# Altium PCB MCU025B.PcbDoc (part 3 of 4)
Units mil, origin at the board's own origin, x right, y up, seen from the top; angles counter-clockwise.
Board outline 2300 x 6150 mil, 6 copper layers (Top Signal, GND, Middle Signal, PWR, GND2, Bottom Signal), stack 61.64 mil thick; 237 components, 197 nets, 910 pads, 404 vias.
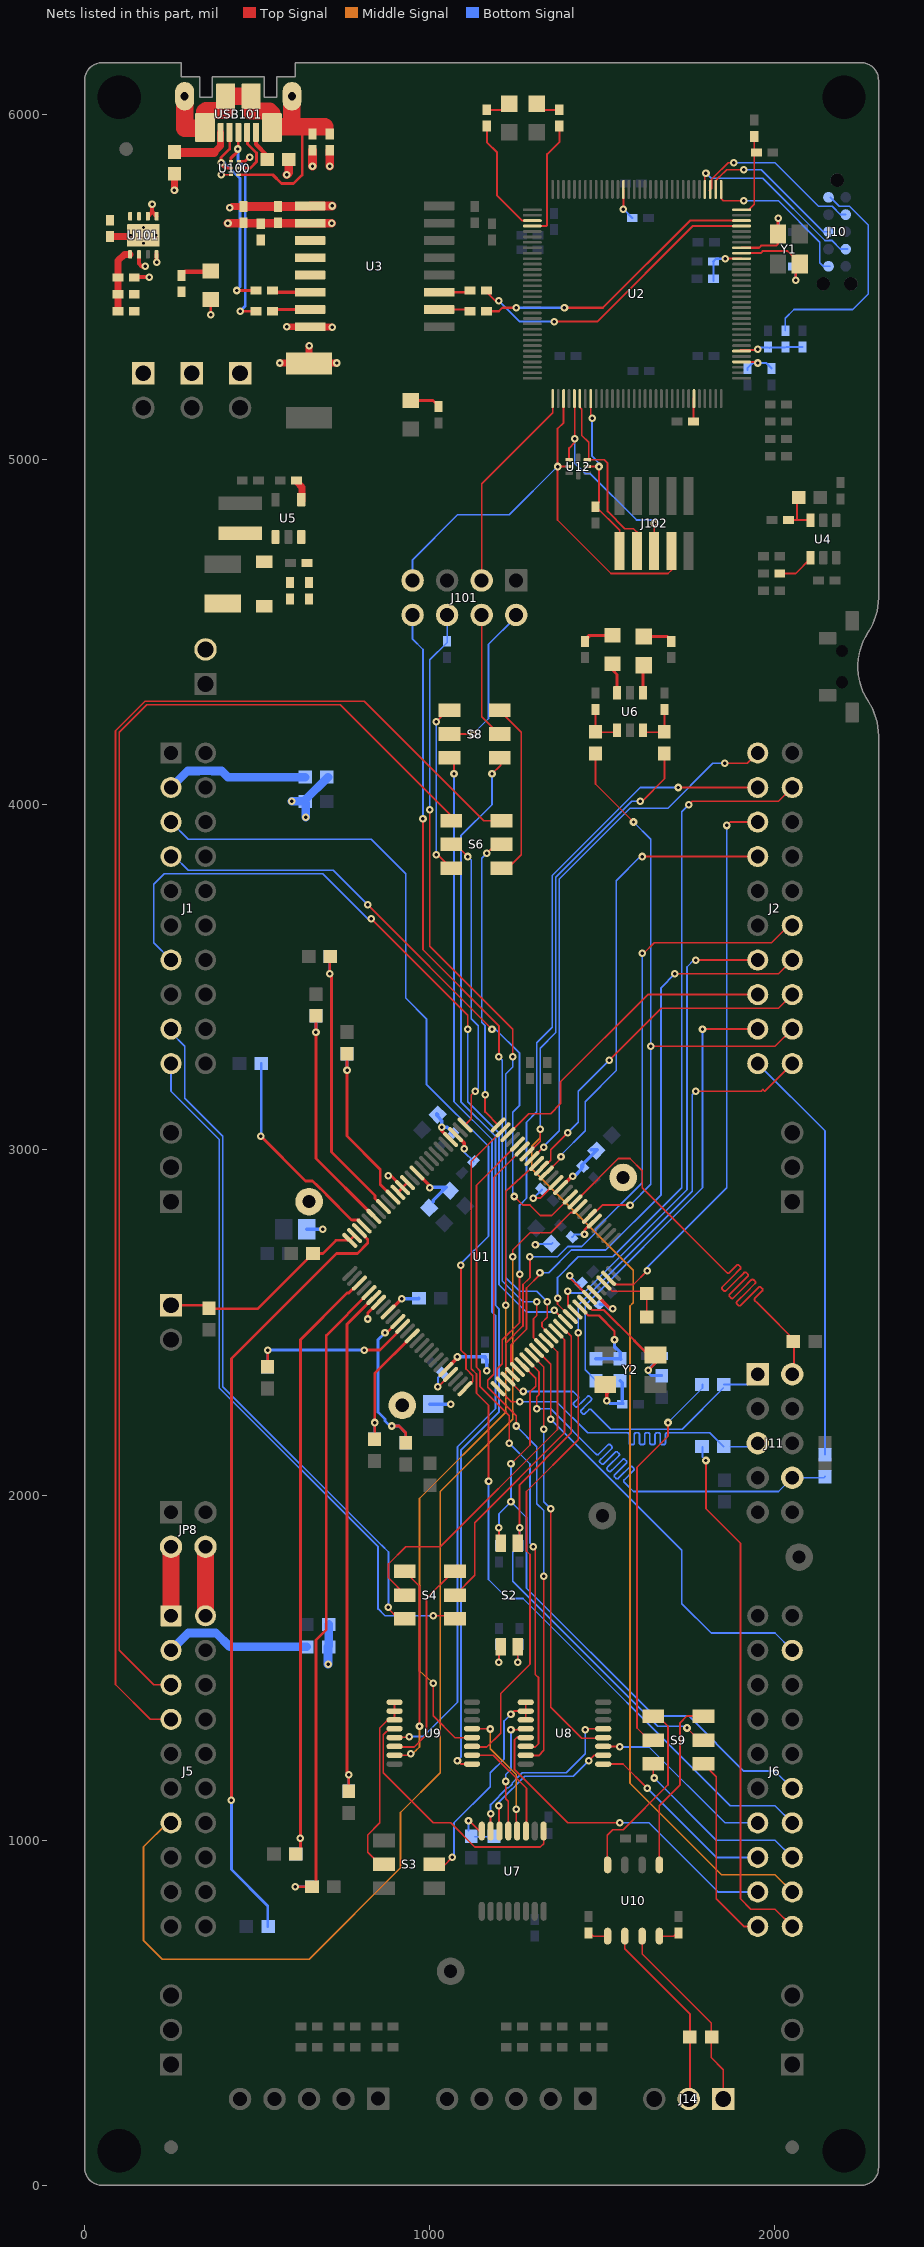
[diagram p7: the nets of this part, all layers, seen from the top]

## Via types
v1: diameter 22, hole 10, Top Signal to Bottom Signal, tented both sides, 400 vias
v2: diameter 19.68, hole 7.87, Top Signal to Bottom Signal, 4 vias

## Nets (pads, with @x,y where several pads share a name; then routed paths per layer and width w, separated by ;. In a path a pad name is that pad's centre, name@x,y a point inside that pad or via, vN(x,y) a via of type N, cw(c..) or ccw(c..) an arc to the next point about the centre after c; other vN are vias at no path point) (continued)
GPIO7_FSITXCLK: J11.2 R45.1 U1.84 | length 1583.5
  Top Signal w5: U1.84@1420.73,2849.38 1546.35,2975 1580,2975 1615,2940 1615,2890 1858.94,2646.06 1861.06,2643.94 ccw(c1864.24,2647.12) 1867.43,2643.94 1889.22,2665.73 cw(c1892.4,2662.55) 1895.58,2665.73 1899.83,2661.49 cw(c1896.64,2658.31) 1899.83,2655.12 1874.85,2630.15 1847.3,2602.6 ccw(c1850.48,2599.42) 1847.3,2596.24 1851.54,2591.99 ccw(c1854.73,2595.17) 1857.91,2591.99 1885.46,2619.54 1910.43,2644.52 cw(c1913.61,2641.33) 1916.8,2644.52 1921.04,2640.27 cw(c1917.86,2637.09) 1921.04,2633.91 1896.06,2608.94 1868.51,2581.39 ccw(c1871.7,2578.2) 1868.51,2575.02 1872.76,2570.78 ccw(c1875.94,2573.96) 1879.12,2570.78 1906.67,2598.33 1931.64,2623.3 cw(c1934.83,2620.12) 1938.01,2623.3 1942.25,2619.06 cw(c1939.07,2615.88) 1942.25,2612.7 1917.28,2587.72 1889.73,2560.17 ccw(c1892.91,2556.99) 1889.73,2553.81 1893.97,2549.57 ccw(c1897.15,2552.75) 1900.33,2549.57 1927.88,2577.12 1952.86,2602.09 cw(c1956.04,2598.91) 1959.22,2602.09 1963.46,2597.85 cw(c1960.28,2594.67) 1963.46,2591.48 1941.67,2569.69 ccw(c1944.85,2566.51) 1941.67,2563.33 1948.27,2556.73 1970,2535 2055,2450 2055,2355 J11.2@2050,2350
GPIO8: J2.38 U1.74 | length 1615.3
  Top Signal w5: U1.74@1518.17,2628.06 1536.23,2610 1590,2610 v1(1630,2650) ; v1(1860,3940) 1870,3950 J2.38@1950,3950
  Bottom Signal w5: v1(1630,2650) 1630,2660 1860,2890 v1(1860,3940)
GPIO9: J2.37 U1.90 | length 1370.1
  Top Signal w5: U1.90@1337.22,2932.89 1380,2975.68 v1(1380,2980) ; v1(1615,3850) J2.37@1950,3850
  Bottom Signal w5: v1(1380,2980) 1380,2985 1450,3055 1450,3140 1540,3230 1540,3780 1610,3850 v1(1615,3850)
GPIO10: J2.40 U1.93 | length 1570.2
  Top Signal w5: U1.93@1295.46,2974.65 1328.8,3008 v1(1330,3008) ; v1(1855,4120) 1920,4120 J2.40@1950,4150
  Bottom Signal w5: v1(1330,3008) 1330,3010 1375,3055 1375,3785 1580,3990 1690,3990 1820,4120 v1(1855,4120)
GPIO11: J2.39 U1.52 | length 2246.7
  Top Signal w5: U1.52@1211.94,2321.83 1195.45,2338.32 1195.45,2365.45 1210,2380 1210,2450 1260,2500 v1(1260,2640) ; v1(1720,4050) J2.39@1950,4050
  Bottom Signal w5: v1(1260,2640) 1260,2840 1280,2860 1280,3080 1310,3110 1310,3310 1355,3355 1355,3795 1610,4050 v1(1720,4050)
GPIO12_BP: J6.11 R47.2 | length 1538.7
  Top Signal w5: v1(1800,2100) 1800,1960 1900,1860 1900,830 1930,800 2000,800 J6.11@2050,750
  Bottom Signal w5: R47.2@1790,2140 1790,2110 v1(1800,2100)
GPIO12_FSIRXD0: J11.5 R47.1 U1.51 | length 1046.4
  Top Signal w5: U1.51@1198.02,2307.91 1235.93,2270 v1(1260,2270)
  Bottom Signal w5: v1(1260,2270) 1367,2270 1457,2180 1555,2180 1562.5,2180 1573,2180 cw(c1573,2175.5) 1577.5,2175.5 1577.5,2150.74 ccw(c1582,2150.74) 1582,2146.24 1588,2146.24 ccw(c1588,2150.74) 1592.5,2150.74 1592.5,2175.5 cw(c1597,2175.5) 1597,2180 1603,2180 cw(c1603,2175.5) 1607.5,2175.5 1607.5,2150.74 ccw(c1612,2150.74) 1612,2146.24 1618,2146.24 ccw(c1618,2150.74) 1622.5,2150.74 1622.5,2175.5 cw(c1627,2175.5) 1627,2180 1633,2180 cw(c1633,2175.5) 1637.5,2175.5 1637.5,2150.74 ccw(c1642,2150.74) 1642,2146.24 1648,2146.24 ccw(c1648,2150.74) 1652.5,2150.74 1652.5,2175.5 cw(c1657,2175.5) 1657,2180 1663,2180 cw(c1663,2175.5) 1667.5,2175.5 1667.5,2150.74 ccw(c1672,2150.74) 1672,2146.24 1678,2146.24 ccw(c1678,2150.74) 1682.5,2150.74 1682.5,2175.5 cw(c1687,2175.5) 1687,2180 1690,2180 1811.5,2180 R47.1@1851.5,2140 ; R47.1@1870,2140 1940,2140 J11.5@1950,2150
GPIO13: J1.3 U1.50 | length 2390
  Top Signal w5: v1(1090,2666) 1090,2420 1105,2405 1105,2365 1124.07,2345.93 1124.07,2330 U1.50@1101.98,2307.91
  Bottom Signal w5: J1.3@250,3950 300,3900 830,3900 930,3800 930,3440 990,3380 990,3190 1170,3010 1170,2750 1090,2670 v1(1090,2666)
GPIO14: U1.96 U8.14 | length 1899.3
  Top Signal w5: v1(1230,2150) 1230,2230 1145,2315 1145,2360 1135,2370 1135,2897.71 U1.96@1253.7,3016.41 ; U8.14@1280,1270 1305,1270 1315,1280 1315,1470 1305,1480 1305,1845 v1(1300,1850)
  Bottom Signal w5: v1(1230,2150) 1290,2090 1290,1860 v1(1300,1850)
GPIO14_BP: J6.32 U8.13 | length 972.8
  Top Signal w5: U8.13@1277.8,1297.2 1252.2,1297.2 1245,1290 1245,1205 1400,1050 v1(1550,1050)
  Bottom Signal w5: v1(1550,1050) 1635,1050 1835,850 J6.32@1950,850
GPIO14_Q2A: U7.5 U8.12 | length 348.1
  Top Signal w5: v1(1220,1170) 1220,1120 1227.2,1112.8 U7.5@1227.2,1026.14 ; v1(1235,1320) U8.12@1280,1320
  Bottom Signal w5: v1(1220,1170) 1220,1190 1235,1205 v1(1235,1320)
GPIO15: U1.95 U8.15 | length 1907.3
  Top Signal w5: 1167.61,2329.89 1167.61,2312.39 1250,2230 v1(1250,2200) ; 1167.61,2330 1167.61,2332.61 1185,2350 1185,2919.87 U1.95@1267.62,3002.49 ; U8.15@1280,1245 1315,1245 1330,1260 v1(1330,1765)
  Bottom Signal w5: v1(1250,2200) 1310,2140 1310,1975 1330,1955 v1(1330,1765)
GPIO15_BP: J6.33 U8.1 | length 559.8
  Top Signal w5: U8.1@1502.2,1220.43 1559.57,1220.43 v1(1630,1150)
  Bottom Signal w5: v1(1630,1150) 1830,950 J6.33@1950,950
GPIO15_Q2B: U7.6 U8.2 | length 438.7
  Top Signal w5: U7.6@1200,1030 v1(1200,1100) ; v1(1460,1230) 1476.02,1246.02 U8.2@1502.2,1246.02
  Bottom Signal w5: v1(1200,1100) 1200,1110 1231.5,1141.5 1231.81,1141.5 1248.5,1158.2 1248.5,1158.5 1275,1185 1415,1185 v1(1460,1230)
GPIO16: J2.15 U1.54 | length 1921.9
  Top Signal w5: U1.54@1240.33,2349.67 U1.54@1239.78,2349.67 1239.78,2350.22 1220,2370 1220,2440 1270,2490 1270,2610 1290,2630 v1(1290,2690) ; v1(1615,3570) 1618,3570 1619,3569 1650,3600 1990,3600 J2.15@2040,3650
  Bottom Signal w5: v1(1290,2690) 1370,2690 1400,2720 1440,2720 1480,2760 1480,2770 1615,2905 v1(1615,3570)
GPIO17: J2.14 U1.55 | length 1781.5
  Top Signal w5: U1.55@1253.7,2363.59 1235,2382.29 1235,2435 1280,2480 1280,2600 1320,2640 1319,2641 v1(1319,2644) ; v1(1710,3510) 2010,3510 J2.14@2050,3550
  Bottom Signal w5: v1(1319,2644) 1344,2644 1410,2710 1510,2710 1670,2870 1670,3470 v1(1710,3510)
GPIO18_BP: J2.32 R28.1 | length 1332.3
  Top Signal w5: v1(1790,3350) J2.32@1950,3350
  Bottom Signal w5: R28.1@1481.21,2331.43 1450,2362.65 1450,2550 1790,2890 v1(1790,3350)
GPIO18_X2: R28.2 R31.2 U1.68 | length 355.5
  Top Signal w6: U1.68@1434.65,2544.54 1459.2,2520 1490,2520 1535,2475 v1(1535,2450)
  Bottom Signal w10: v1(1535,2450) 1535,2430 1551.21,2413.79 R31.2@1551.21,2394.43 ; R31.2@1550,2395 1549.43,2394.43 R28.2@1481.21,2394.43 1550,2394.42 R31.2@1551.21,2394.43
GPIO22: J5.7 U1.83 | length 3427.8
  Top Signal w5: v1(1240,2690) 1240,2710 1290,2760 1350,2760 1408.5,2818.5 1417.7,2818.5 U1.83@1434.65,2835.46
  Middle Signal w5: J5.7@250,1050 240,1050 170,980 170,710 225,655 650,655 915,920 915,1080 1030,1195 1030,2010 1240,2220 v1(1240,2690)
GPIO23: J2.12 R38.1 U1.81 | length 1962.8
  Top Signal w5: U1.81@1462.49,2807.62 1467.62,2807.62 1500,2840 v1(1580,2840) ; R38.1@1480,4150 R38.1@1480,4148.5 1480,4060 v1(1590,3950) ; v1(1640,3300) 2000,3300 J2.12@2050,3350
  Bottom Signal w5: v1(1580,2840) 1640,2900 v1(1640,3300) 1640,3900 v1(1590,3950)
GPIO24: J6.15 R33.1 S2.2 U1.56 | length 1908
  Top Signal w5: S2.2@1200,1860 v1(1200,1905) ; v1(1235,2090) 1290,2145 1290,2298.84 1306.5,2315.34 1306.5,2338.63 U1.56@1267.62,2377.51
  Bottom Signal w5: R33.1@1200,1853.62 v1(1200,1905) 1200,1945 v1(1235,1980) ; v1(1235,2090) v1(1235,1980) ; J6.15@2050,1150 2000,1200 1910,1200 1750,1360 1650,1360 1280,1730 1280,1935 v1(1235,1980)
GPIO25_BP: J2.31 R72.2 | length 1214.3
  Bottom Signal w5: J2.31@1950,3250 2145,3055 R72.2@2145,2116.5
GPIO25_FSITXD1: J11.8 R72.1 U1.57 | length 1516.7
  Top Signal w5: U1.57@1281.54,2391.43 1316.5,2356.47 1316.5,2291.5 1310,2285 v1(1310,2250)
  Bottom Signal w5: v1(1310,2250) 1350,2250 1480,2120 1482.12,2117.88 ccw(c1485.3,2121.06) 1488.49,2117.88 1516.08,2145.48 cw(c1519.27,2142.3) 1522.45,2145.48 1526.69,2141.24 cw(c1523.51,2138.05) 1526.69,2134.87 1495.91,2104.09 1492.93,2101.11 ccw(c1496.11,2097.93) 1492.93,2094.75 1497.17,2090.5 ccw(c1500.35,2093.69) 1503.54,2090.5 1506.52,2093.48 1537.3,2124.26 cw(c1540.48,2121.08) 1543.66,2124.26 1547.9,2120.02 cw(c1544.72,2116.84) 1547.9,2113.66 1517.12,2082.88 1514.14,2079.9 ccw(c1517.32,2076.71) 1514.14,2073.53 1518.39,2069.29 ccw(c1521.57,2072.47) 1524.75,2069.29 1527.73,2072.27 1558.51,2103.05 cw(c1561.69,2099.87) 1564.87,2103.05 1569.12,2098.81 cw(c1565.94,2095.63) 1569.12,2092.44 1538.34,2061.66 1535.36,2058.68 ccw(c1538.54,2055.5) 1535.36,2052.32 1539.6,2048.08 ccw(c1542.78,2051.26) 1545.96,2048.08 1548.94,2051.06 1579.72,2081.84 cw(c1582.91,2078.66) 1586.09,2081.84 1590.33,2077.6 cw(c1587.15,2074.41) 1590.33,2071.23 1562.73,2043.63 ccw(c1565.91,2040.45) 1562.73,2037.27 1567.36,2032.64 1590,2010 2010,2010 J11.8@2050,2050 2141.5,2050 R72.1@2145,2053.5
GPIO26: U1.58 U8.4 | length 1235.2
  Top Signal w5: U1.58@1295.46,2405.35 1330,2370.81 v1(1330,2190) ; v1(1350,1960) 1350,1750 1350,1730 1350,1385 1440,1295 U8.4@1505,1295
  Bottom Signal w5: v1(1330,2190) 1330,1980 v1(1350,1960)
GPIO26_BP: J6.34 U8.3 | length 539.6
  Top Signal w5: U8.3@1502.2,1271.61 1548.39,1271.61 v1(1550,1270)
  Bottom Signal w5: v1(1550,1270) 1635,1270 1855,1050 J6.34@1950,1050
GPIO26_Q2I: U7.7 U8.5 | length 534.8
  Top Signal w5: v1(1176,1077) 1176,1034 U7.7@1180,1030 ; v1(1450,1320) 1452.8,1322.8 U8.5@1502.2,1322.8
  Bottom Signal w5: v1(1176,1077) 1176,1103 1224.5,1151.5 1227.66,1151.5 1238.5,1162.34 1238.5,1165.5 1268,1195 1395,1195 1450,1250 v1(1450,1320)
GPIO27: J6.19 U1.59 | length 1291.5
  Top Signal w5: U1.59@1309.38,2419.27 1350,2378.65 v1(1350,2220)
  Bottom Signal w5: v1(1350,2220) 1730,1840 1730,1685 1815,1600 2000,1600 J6.19@2050,1550 J6.19@2055,1545
GPIO28: S6.2 U1.1 | length 868.5
  Top Signal w5: S6.2@1065,3885 1075,3885 v1(1110,3850) ; U1.1@1100,3070 1120,3090 1120,3159 v1(1131,3170)
  Bottom Signal w5: v1(1110,3850) 1120,3840 1120,3380 1140,3360 1140,3179 v1(1131,3170)
GPIO28_BP: J5.3 S6.1 | length 3994.1
  Top Signal w5: J5.3@250,1450 200,1450 100,1550 100,4210 180,4290 740,4290 1062.17,3967.83 S6.1@1062.17,3953.9
GPIO28_SCIRX: S6.3 S8.6 | length 507.8
  Top Signal w5: v1(1018.5,3854.86) 1018.27,3855.09 1018.27,3860 S6.3@1062.17,3816.1 ; v1(1018.5,4240.14) 1018.64,4240 1048.64,4270 S8.6@1060,4270
  Bottom Signal w5: v1(1018.5,3854.86) 1018.5,4233.5 1020,4235 1020,4238.64 v1(1018.5,4240.14)
GPIO29: S6.5 U1.100 | length 867.3
  Top Signal w5: v1(1160,3160) 1160,3110 U1.100@1200,3070 ; v1(1165,3860) 1190,3885 S6.5@1205,3885
  Bottom Signal w5: v1(1160,3160) 1160,3360 1150,3370 1150,3845 v1(1165,3860)
GPIO29_BP: J5.4 S6.4 | length 4264
  Top Signal w5: J5.4@250,1350 190,1350 89,1451 89,4214.56 174.44,4300 810,4300 1156.1,3953.9 S6.4@1207.83,3953.9
GPIO29_SCITX: S6.6 S8.3 | length 520.2
  Top Signal w5: S8.3@1200,4275 1265,4210 1265,3855 1226.1,3816.1 S6.6@1207.83,3816.1
GPIO30: J2.33 U1.98 | length 932.6
  Top Signal w5: U1.98@1225.86,3045.86 U1.98@1225.86,3044.25 1286.61,3105 ; 1285,3105 1286.61,3105 ; J2.33@1950,3450 1631.61,3450 1378.31,3196.69 1378.31,3133.31 1350,3105 1286.61,3105
GPIO31: J6.14 U1.99 | length 2534
  Top Signal w5: v1(1170,2040) 1170,2260 1135,2295 1135,2350.56 1120,2365.56 1120,2966.23 U1.99@1211.94,3058.17
  Bottom Signal w5: v1(1170,2040) 1170,1755 1225,1700 1270,1700 1870,1100 2000,1100 J6.14@2050,1050
GPIO32: R34.1 S2.1 S9.5 U1.64 | length 1598.9
  Top Signal w5: S2.1@1260,1860 v1(1260,1905) 1260,2030 1410,2180 1410,2460 1381.14,2488.86 U1.64@1378.97,2488.86 ; v1(1745,1325) S9.5@1780,1290
  Bottom Signal w5: v1(1260,1905) R34.1@1260,1853.62 1240,1833.62 1240,1750 1660,1330 1740,1330 v1(1745,1325)
GPIO32_BP: J6.31 S9.6 | length 559.6
  Top Signal w5: S9.6@1792.83,1221.1 1830,1183.94 1830,830 1910,750 J6.31@1950,750
GPIO32_CANTX: S9.4 U10.1 | length 513.1
  Top Signal w5: U10.1@1665,925 U10.1@1665,928.35 1665,1100 1725,1160 1725,1340 1745,1360 S9.4@1790,1360
GPIO33_ALT: R46.2 S9.2 | length 1135.4
  Top Signal w5: S9.2@1647.17,1290 1635,1290 1600,1325 1600,2080 1690,2170 v1(1690,2210)
  Bottom Signal w5: v1(1690,2210) 1790,2310 R46.2@1790,2320
GPIO33_BP: J6.13 S9.3 | length 537.5
  Top Signal w5: S9.3@1647.17,1221.1 1647.17,1182.83 v1(1650,1180)
  Bottom Signal w5: v1(1650,1180) 1830,1000 2000,1000 J6.13@2050,950
GPIO33_CANRX: S9.1 U10.4 | length 545.9
  Top Signal w5: U10.4@1514,927 1514,1014 1530,1030 1560,1030 1690,1160 1690,1330 1660,1360 S9.1@1650,1360
GPIO33_FSIRXCLK: J11.1 R46.1 U1.53 | length 1066
  Top Signal w5: U1.53@1225.86,2335.75 1261.61,2300 v1(1270,2300)
  Bottom Signal w5: 1349.61,2300 v1(1270,2300) 1415,2300 ; 1410,2300 1415,2300 ; R46.1@1850,2310 1730.82,2190.82 1524.18,2190.82 1469.59,2245.41 1467.47,2247.53 ccw(c1464.28,2244.35) 1461.1,2247.53 1448.89,2235.32 cw(c1445.71,2238.5) 1442.53,2235.32 1438.28,2239.56 cw(c1441.47,2242.75) 1438.28,2245.93 1453.68,2261.32 1467.23,2274.87 ccw(c1464.05,2278.06) 1467.23,2281.24 1462.99,2285.48 ccw(c1459.81,2282.3) 1456.62,2285.48 1443.07,2271.93 1427.68,2256.53 cw(c1424.5,2259.72) 1421.31,2256.53 1417.07,2260.78 cw(c1420.25,2263.96) 1417.07,2267.14 1429.28,2279.35 ccw(c1426.1,2282.54) 1429.28,2285.72 1422.5,2292.5 1415,2300 ; R46.1@1851.5,2320 1920,2320 J11.1@1950,2350
GPIO34: J6.12 R39.1 U1.94 | length 3980.7
  Top Signal w5: U1.94@1281.54,2988.57 1283.57,2988.57 1320,3025 v1(1320,3060) ; v1(1610,4010) 1615,4010 1680,4075 1680,4140 R39.1@1690,4150
  Middle Signal w5: v1(1320,3060) 1320,3035 1295,3010 1295,2945 1589,2651 1589,2556.75 1580,2547.75 1580,1165 1845,900 2000,900 J6.12@2050,850
  Bottom Signal w5: v1(1320,3060) 1320,3295 1365,3340 1365,3790 1585,4010 v1(1610,4010)
GPIO35: S4.5 U1.63 | length 906.7
  Top Signal w5: S4.5@1072.83,1710 1130,1767.17 1130,1920 1390,2180 1390,2450 U1.63@1365.06,2474.94
GPIO35_ALT: S4.4 U9.14 | length 615
  Top Signal w5: U9.14@900,1270 955,1270 990,1305 990,1700 1068.9,1778.9 S4.4@1072.83,1778.9
GPIO35_BP: J1.10 S4.6 | length 2071
  Top Signal w5: v1(1010,1650) 1070,1650 S4.6@1080,1640
  Bottom Signal w5: J1.10@250,3250 250,3170 390,3030 390,2310 850,1850 850,1670 870,1650 v1(1010,1650)
GPIO35_Q1A: U7.1 U9.12 | length 736.5
  Top Signal w5: U9.12@895,1325 885,1325 865,1305 865,1195 1010,1050 1060,1050 1130,980 1320,980 1330,990 U7.1@1330,1020
GPIO35_SCIRX: S8.4 U9.13 | length 3063.8
  Top Signal w5: U9.13@895.59,1295 U9.13@897.8,1297.2 ; U9.13@898,1298 938,1298 v1(940,1300) ; S8.4@1055,4135 1070,4120 v1(1070,4090)
  Bottom Signal w5: v1(940,1300) 980,1300 1080,1400 1080,2140 1190,2250 1190,2520 1180,2530 1180,3030 1070,3140 v1(1070,4090)
GPIO37: S4.2 U1.61 | length 1032.9
  Top Signal w5: S4.2@930,1710 880,1760 880,1800 930,1850 1030,1850 1370,2190 1370,2414.32 U1.61@1337.22,2447.11
GPIO37_ALT: S4.1 U9.15 | length 608.8
  Top Signal w5: U9.15@897.8,1246.02 941.02,1246.02 v1(945,1250) ; S4.1@927.17,1778.9 970,1736.06 970,1340 v1(970,1330)
  Middle Signal w5: v1(945,1250) 950,1250 960,1260 970,1270 v1(970,1330)
GPIO37_BP: J1.9 S4.3 | length 2003.9
  Top Signal w5: v1(880,1675) 880,1670 910,1640 S4.3@930,1640
  Bottom Signal w5: J1.9@250,3350 250,3340 290,3300 290,3150 400,3040 400,2314.14 860,1854.14 860.86,1854.14 880,1835 v1(880,1675)
GPIO37_Q1B: U7.3 U9.2 | length 317.6
  Top Signal w5: U9.2@1122.2,1246.02 1183.98,1246.02 1280,1150 U7.3@1280,1030
GPIO37_SCITX: S8.1 U9.1 | length 3099.1
  Top Signal w5: v1(1080,1230) 1089.57,1220.43 U9.1@1122.2,1220.43 ; v1(1180,4090) 1205,4115 S8.1@1205,4140
  Bottom Signal w5: v1(1080,1230) 1090,1240 1090,2130 1200,2240 1200,2540 1190,2550 1190,3040 1090,3140 1090,3910 1180,4000 v1(1180,4090)
GPIO39: J2.13 U1.91 | length 1005.4
  Top Signal w5: U1.91@1323.3,2946.81 1326.81,2946.81 1350,2970 1350,3000 v1(1400,3050) ; v1(1520,3260) 1670,3410 2010,3410 J2.13@2050,3450
  Bottom Signal w5: v1(1400,3050) 1430,3080 1430,3170 v1(1520,3260)
GPIO40: J1.4 U1.85 | length 1882.5
  Top Signal w5: v1(820,3710) v1(1180,3350) ; v1@1245,2869.34 v1(1245,2865) 1270,2840 1290,2840 1320,2810 1353.52,2810 U1.85@1406.81,2863.3
  Bottom Signal w5: J1.4@250,3850 260,3850 300,3810 720,3810 v1(820,3710) ; v1(1180,3350) 1190,3350 1260,3280 1260,3129.11 1240,3109.11 1240,2870 v1(1245,2865)
GPIO56: J1.7 U1.65 | length 2394.5
  Top Signal w5: v1(830,3670) 1110,3390 v1(1110,3350) ; v1(1360,2535) 1363,2535 1364,2534 1364.32,2534.32 1365.68,2534.32 1365.68,2530 U1.65@1392.89,2502.78
  Bottom Signal w5: J1.7@250,3550 200,3600 200,3770 230,3800 690,3800 820,3670 v1(830,3670) ; v1(1110,3350) 1110,3140 1200,3050 1200,2610 1280,2530 1355,2530 v1(1360,2535)
GPIO57: J2.19 U1.66 | length 2035.2
  Top Signal w5: v1(1370,2570) 1370,2553.52 U1.66@1406.81,2516.7 ; v1(1750,4000) 1760,4010 2010,4010 J2.19@2050,4050
  Bottom Signal w5: v1(1370,2570) 1370,2630 1430,2690 1530,2690 1730,2890 1730,3980 v1(1750,4000)
GPIO58: J2.34 U1.67 | length 1397.6
  Top Signal w5: v1(1400,2590) 1400,2551.35 U1.67@1420.73,2530.62 ; v1(1770,3550) J2.34@1950,3550
  Bottom Signal w5: v1(1400,2590) 1405,2585 1445,2585 1745,2885 1745,3530 1765,3550 v1(1770,3550)
GPIO59: U1.92 U9.4 | length 1902
  Top Signal w5: v1(1010,1454.34) 1010,1360 1073,1297 U9.4@1124,1297 ; v1(1220,2550) 1220,2880 U1.92@1309.38,2960.73
  Middle Signal w5: v1(1010,1454.34) 1004.69,1459.65 970,1490 970,1990 1220,2240 v1(1220,2550)
GPIO59_BP: J2.11 U9.3 | length 2516.2
  Top Signal w5: U9.3@1125,1270 1165,1270 1205,1310 1205,1425 1290,1510 1290,1827.75 1280,1837.75 1280,2010 1430,2160 v1(1430,2470) ; v1(1770,3170) 1960,3170 1965,3175 1970,3170 J2.11@2050,3250
  Bottom Signal w5: v1(1430,2470) 1430,2550 1760,2880 1760,3160 v1(1770,3170)
GPIO59_Q1I: U7.4 U9.5 | length 405.4
  Top Signal w5: U9.5@1122.2,1322.8 1177.2,1322.8 v1@1180,1320 ; U7.4@1250,1030 v1(1250,1090) ; U7.4@1252.8,1002.8 U7.4@1252.8,1026.14
  Middle Signal w5: v1@1180,1320 1175,1315 1175,1265 1250,1190 v1(1250,1090)
  other v1: 1175,1322
ITCK: J10.4 U2.100 | length 549.3
  Top Signal w5: U2.100@1796.85,5783.15 1796.85,5826.85 v1(1800,5830)
  Bottom Signal w5: v1(1800,5830) 1815,5815 1965,5815 2145,5635 2165,5635 2165.47,5634.53 2190,5610 J10.4@2205,5610 J10.4@2210,5610
ITDI: J10.8 U2.98 | length 444.7
  Top Signal w5: U2.98@1828.35,5783.15 1828.35,5808.35 1831.66,5811.66 1831.66,5811.92 1838.94,5819.21 1839.21,5819.21 1860,5840 v1(1910,5840)
  Bottom Signal w5: v1(1910,5840) 1960,5840 2140,5660 J10.8@2155,5660 J10.8@2160,5660
ITDO: J10.6 U2.97 | length 459.4
  Top Signal w5: U2.97@1844.09,5783.15 1844.09,5755.91 1850,5750 v1(1910,5750)
  Bottom Signal w5: v1(1910,5750) 2010,5750 2130,5630 2130,5570 2140,5560 J10.6@2155,5560 J10.6@2160,5560
ITMS: J10.2 U2.99 | length 505.5
  Top Signal w5: U2.99@1810,5780 1815.91,5785.91 1815.91,5811.92 1823.19,5819.21 1823.39,5819.21 1864.18,5860 v1(1880,5860)
  Bottom Signal w5: v1(1880,5860) 2000,5860 2126,5734 2166,5734 2190,5710 J10.2@2205,5710
NetC3_1: C3.1 C4.1 D1.1 JP9.2 R7.2
NetC3_2: C3.2 R7.1 R9.2 U5.3
NetC8_1: C8.1 R6.1 U4.6 | length 134.6
  Top Signal w5: C8.1@2038.62,4825 2065,4825 ; R6.1@2070,4890 2063.62,4883.62 2063.62,4826.38 2065,4825 ; U4.6@2105,4825 2065,4825
NetC26_2: C26.2 R14.1 U1.18 | length 838.9
  Top Signal w8: R14.1@710,3560 v1(710,3510) 715,3505 715,2994 841.4,2867.6 841.4,2859.4 U1.18@865.35,2835.46
  Bottom Signal w8: v1(710,3510) C26.2@710,3560
NetC27_2: C27.2 R16.1 U1.30 | length 1887.6
  Top Signal w8: v1(610,865) R16.1@657.01,865 ; R16.1@658.5,865 R16.1@658.5,866.5 ; R16.1@660,865 670,875 670,1580 700,1610 700,2462.71 U1.30@823.59,2586.3
  Bottom Signal w8: v1(610,865) C27.2@658.5,865 C27.2@660,865
NetC28_2: C28.2 R17.1 U1.20 | length 700.8
  Top Signal w8: R17.1@670,3390 R17.1@670,3388.5 v1(670,3341) 670,2975.13 U1.20@837.51,2807.62
  Bottom Signal w8: v1(670,3341) C28.2@670,3388.5 C28.2@670,3390
NetC29_2: C29.2 R18.1 U1.31 | length 1515.1
  Top Signal w8: R18.1@765,1140 R18.1@765,1141.5 v1(765,1190) 760,1195 760,2494.87 U1.31@837.51,2572.38
  Bottom Signal w8: C29.2@765,1141.5 v1(765,1190)
NetC30_2: C30.2 R20.1 U1.16 | length 519.4
  Top Signal w8: R20.1@760,3280 R20.1@760,3278.5 v1(760,3231) 760,3040 856,2944 856,2900.48 U1.16@893.19,2863.3
  Bottom Signal w8: v1(760,3231) C30.2@760,3278.5
NetC31_2: C31.2 R21.1 U1.28 | length 1786.8
  Top Signal w8: R21.1@610,960 625,975 v1(625,1005) 625,2450 760,2585 765,2585 794.14,2614.14 U1.28@795.75,2614.14
  Bottom Signal w8: C31.2@611.5,960 610,961.5 625,976.5 v1(625,1005)
NetC32_1: C32.1 R19.2 U1.36 | length 503.5
  Top Signal w8: v1(870,2470) 874.32,2470 U1.36@907.11,2502.78 ; v1(890,2200) 910,2200 930,2180 R19.2@930,2151.5 R19.2@930,2150
  Bottom Signal w8: v1(870,2470) 850,2450 850,2240 870,2220 870,2215 885,2200 v1(890,2200) 910,2200 930,2180 C32.1@930,2151.5
NetC33_1: C33.1 R22.2 U1.37 | length 530.8
  Top Signal w8: v1(530,2420) 530,2381.5 540,2371.5 R22.2@540,2370 ; v1(810,2420) 855,2420 U1.37@925,2490
  Bottom Signal w8: C33.1@540,2371.5 530,2381.5 v1(530,2420) v1(810,2420)
NetC34_1: C34.1 R25.2 U1.39 | length 394.6
  Top Signal w8: R25.2@840,2160 R25.2@840,2161.5 v1(840,2210) 840,2352.16 U1.39@948.86,2461.03
  Bottom Signal w8: C34.1@840,2161.5 v1(840,2210)
NetC35_1: C35.1 C36.1 J15.1 U1.24 U1.25 | length 620.9
  Top Signal w8: J15.1@250,2550 350,2550 360,2540 501.5,2540 C36.1@661.5,2700 690,2700 728.02,2738.02 U1.25@767.91,2738.02 ; U1.25@770,2740 781.83,2751.83 U1.24@781.83,2751.94
NetC38_1: C38.1 R31.1 Y2.1 | length 168.6
  Top Signal w10: Y2.1@1508.38,2319.62 1523.43,2304.57 1513,2294.14 v1(1513,2273)
  Bottom Signal w8: v1(1513,2273) 1521,2265 C38.1@1560,2265
  Bottom Signal w10: R31.1@1551.21,2331.43 1557.59,2325.06 C38.1@1557.59,2273
NetC50_1: C50.1 R62.2 U2.96 | length 1092.2
  Top Signal w5: U2.96@1900,5724.28 U2.96@1924.28,5724.28 ; U2.96@1900,5724.28 U2.96@1924.28,5724.28 ; U2.96@1900,5724.28 U2.96@1924.28,5724.28 ; U2.96@1900,5724.28 U2.96@1924.28,5724.28 ; U2.96@1900,5724.28 U2.96@1924.28,5724.28 ; U2.96@1924.28,5724.28 1940,5740 ; 1940,5740 C50.1@1940,5890 ; 1940,5740 C50.1@1940,5890 ; 1940,5740 C50.1@1940,5890 ; 1940,5740 C50.1@1940,5890 ; 1940,5851.11 C50.1@1940,5890 ; 1940,5851.11 R62.2@1940,5936.38 ; 1940,5851.11 C50.1@1940,5890 ; C50.1@1940,5890 R62.2@1940,5936.38 ; C50.1@1940,5890 R62.2@1940,5936.38 ; C50.1@1940,5890 R62.2@1940,5936.38 ; C50.1@1940,5890 R62.2@1940,5936.38
NetC59_1: C59.1 C60.1 C61.1 U2.87 U2.115 | length 237.7
  Top Signal w6: v1(1560,5725) 1560.63,5725.63 U2.115@1560.63,5783.15 ; v1(1856,5582) 1862,5582 1862.36,5582.36 U2.87@1903.15,5582.36
  Bottom Signal w6: v1(1560,5725) 1561.38,5725 C61.1@1586.38,5700 ; C59.1@1821,5574 1829,5582 1846,5582 v1(1856,5582) ; C60.1@1821.62,5517.62 C60.1@1821.62,5524 1821.62,5572.62 C59.1@1823,5574
NetC62_1: C62.1 U2.89 Y1.3 | length 227.7
  Top Signal w6: U2.89@1903.15,5613.86 1953.86,5613.86 1960,5620 2004,5620 2009,5625 2008,5626 Y1.3@2008,5653
  Top Signal w8: Y1.3@2008.5,5653.31 2008.5,5698.5 v1(2010,5700)
  Bottom Signal w8: C62.1@2006.38,5660 2010,5663.62 v1(2010,5700)
NetC63_1: C63.1 U2.88 Y1.1 | length 283.5
  Top Signal w6: U2.88@1903.15,5598.11 1957.89,5598.11 1964,5604.22 2036.78,5604.22 2073,5568 Y1.1@2073,5566
  Top Signal w8: v1(2060,5520) 2060,5555.2 Y1.1@2071.5,5566.69
  Bottom Signal w8: C63.1@2053.62,5560 2053.62,5549.37 2060,5542.99 v1(2060,5520)
NetC66_1: C66.1 R70.1 U2.68 | length 137
  Top Signal w6: U2.68@1903.15,5283.15 1946.85,5283.15 v1(1950,5280)
  Bottom Signal w6: R70.1@1920,5260 1920,5265 1935,5280 v1(1950,5280) 1975,5280 1990,5265 C66.1@1990,5263.62
NetC101_1: C101.1 R100.2 U100.1 USB101.6 USB101.7 USB101.8 USB101.9 USB101.10 USB101.11 | length 1103.4
  Top Signal w8: U100.1@445.83,5825.31 544.69,5825.31 570,5800 605,5800 630,5825 630,5964.8 630,5965
  Top Signal w50: USB101.10@289.49,6052.91 289.49,5960.51 USB101.11@346.2,5960.51 ; USB101.11@348.05,5962.36 348.05,6008.05 350,6010 ; 351.91,6011.91 408.09,6011.91 USB101.9@408.09,6052.91 USB101.8@481.91,6052.91 481.91,6011.91 ; 480,6010 535,6010 541.95,6003.05 USB101.6@541.95,5964.8 ; USB101.6@539.51,5964.8 USB101.6@541.95,5964.8 ; USB101.6@541.95,5962.36 USB101.6@541.95,5964.8 ; USB101.7@600,6052.4 600,5964.8 ; 695.2,5964.8 630,5964.8 600,5964.8 ; USB101.6@541.95,5964.8 600,5964.8
NetC102_2: C102.2 R101.1 R102.2 U101.5 | length 189.4
  Top Signal w20: C102.2@96,5478 96.38,5477.62 R101.1@96.38,5430 ; C102.2@96.38,5478 C102.2@96.38,5479 R102.2@96.38,5528 96.38,5576.38 114.88,5594.88 U101.5@131.61,5594.88
NetC106_2: C106.2 U3.3 U3.4 U3.5
NetD1_2: D1.2 L1.2 U5.1
NetJ5_1: J5.1 JP8.3 | length 200
  Top Signal w50: J5.1@250,1650 JP8.3@250,1850
NetJ5_21: J5.21 JP8.4 | length 200
  Top Signal w50: J5.21@350,1650 JP8.4@350,1850
NetJ10_10: J10.10 R66.1 | length 648.5
  Bottom Signal w5: R66.1@2030,5373.62 2030,5410 2055,5435 2225,5435 2270,5480 2270,5680 2216,5734 2186,5734 J10.10@2160,5760
NetJ14_1: J14.1 R55.2 U10.7 | length 569
  Top Signal w5: U10.7@1615,721.65 1615,670 1815,470 1815,370 1850,335 J14.1@1850,250
NetJ14_2: J14.2 R55.1 U10.6 | length 551.2
  Top Signal w5: U10.6@1565,721.65 1565,685 1753.5,496.5 R55.1@1753.5,430 1753.5,253.5 J14.2@1750,250
NetL100_1: L100.1 USB101.5 | length 91.6
  Top Signal w12: USB101.5@496.18,5948.19 496.18,5913.82 528.5,5881.5 L100.1@528.5,5870
NetL101_1: L101.1 USB101.1 | length 179.3
  Top Signal w20: 374.61,5890 393.82,5909.21 USB101.1@393.82,5948.19
  Top Signal w25: L101.1@261.5,5890 374.61,5890
NetLED0_2: LED0.2 R105.1 | length 169.7
  Top Signal w8: R105.1@280,5535 R105.1@286.5,5541.5 ; LED0.2@361.5,5541.5 R105.1@286.5,5541.5 ; LED0.2@365,5540 LED0.2@365,5545 ; LED0.2@365,5546.34 291.34,5546.34 R105.1@286.5,5541.5
NetLED1_2: LED1.2 R3.1 | length 86.8
  Top Signal w8: LED1.2@945,5171.34 1008.66,5171.34 R3.1@1025,5155
NetLED2_1: LED2.1 R63.1 | length 71.8
  Top Signal w6: R63.1@1165,6013.62 1213.62,6013.62 LED2.1@1230,6030
NetLED3_1: LED3.1 R64.1 | length 71.8
  Top Signal w6: LED3.1@1310,6030 1326.38,6013.62 R64.1@1375,6013.62
NetLED4_1: LED4.1 U6.6 | length 95.2
  Top Signal w5: U6.6@1540,4320 U6.6@1540,4324.13
  Top Signal w8: LED4.1@1530,4410 1530,4390 1542.6,4377.4 U6.6@1542.6,4324.13
NetLED4_2: LED4.2 R29.1 | length 171.5
  Top Signal w8: R29.1@1449.37,4473.46 1465.91,4490 LED4.2@1530,4490 ; R29.1@1450,4480 1461.18,4491.18 LED4.2@1529.37,4491.18
NetLED5_1: LED5.1 R30.1 | length 85.1
  Top Signal w8: LED5.1@1620,4487.34 1687.66,4487.34 R30.1@1700,4475
NetLED5_2: LED5.2 U6.4 | length 81.9
  Top Signal w8: U6.4@1617.4,4324.13 1617.4,4402.4 LED5.2@1620,4405
NetR1_1: R1.1 U3.11 | length 123.3
  Top Signal w6: U3.11@1027.01,5485 R1.1@1115,5485 ; R1.1@1115,5485 R1.1@1120,5490 ; R1.1@1115,5485 R1.1@1120,5490 ; R1.1@1115,5485 R1.1@1120,5490 ; R1.1@1115,5485 R1.1@1120,5490 ; R1.1@1115,5485 R1.1@1120,5490
NetR2_1: R2.1 U3.10 | length 123.3
  Top Signal w6: U3.10@1027.01,5435 R2.1@1115,5435 ; R2.1@1115,5435 R2.1@1120,5430 ; R2.1@1115,5435 R2.1@1120,5430 ; R2.1@1115,5435 R2.1@1120,5430 ; R2.1@1115,5435 R2.1@1120,5430 ; R2.1@1115,5435 R2.1@1120,5430
NetR5_1: R5.1 U4.1 | length 113.5
  Top Signal w5: R5.1@2010,4670 R5.1@2013.62,4670 2060,4670 2102.6,4712.6 U4.1@2102.6,4715.87
NetR8_1: R8.1 U5.4 | length 66.8
  Top Signal w20: R8.1@613.62,4940 613.62,4936.38 630,4920 U5.4@630,4880
NetR13_2: R13.2 U1.23 | length 2274.7
  Top Signal w8: v1(425,1115) 425,2395 730,2700 790,2700 820,2730 820,2740 U1.23@790,2770
  Bottom Signal w8: v1(425,1115) 425,915 530,810 R13.2@530,750
NetR15_2: R15.2 U1.22 | length 613.8
  Top Signal w8: v1(510,3040) 640,2910 660,2910 670,2900 670.71,2900 700,2870.71 700,2870 772.69,2797.31 773.15,2797.77 773.84,2797.77 774.62,2797 792,2797 805.21,2783.79 U1.22@806.21,2783.79
  Bottom Signal w8: v1(510,3040) 511.5,3041.5 R15.2@511.5,3250
NetR23_1: R23.1 R26.2 U1.13 U1.14 U1.15 | length 276.1
  Top Signal w8: v1(880,2925) 887.16,2925 U1.14@921.03,2891.14 ; U1.15@907.11,2877.22 907.22,2877.22 U1.13@935,2905
  Bottom Signal w8: R26.2@636.75,4008.25 R26.2@640,4005 ; R26.2@638.5,4010 R26.2@638.5,4013.5
  Bottom Signal w25: v1(600,4010) R26.2@638.5,4010 ; R26.2@638.5,4013.5 R23.1@705,4080 ; v1(640,3964) R26.2@640,4005
NetR24_1: R24.1 R27.2 U1.32 | length 177.1
  Top Signal w8: v1(820,2510) 820,2527.03 U1.32@851.43,2558.46
  Bottom Signal w10: R24.1@705,1560 R24.1@706.5,1561.5
  Bottom Signal w25: v1(705,1510) R24.1@705,1560 ; R24.1@706.5,1561.5 R27.2@706.5,1625
NetR36_1: R36.1 R38.2 U6.1 | length 126.4
  Top Signal w5: R36.1@1480,4276.38 R38.2@1480,4211.5 1480,4210 U6.1@1540,4210
NetR37_1: R37.1 R39.2 U6.3 | length 136.4
  Top Signal w5: U6.3@1620,4210 R39.2@1690,4210 ; R39.2@1680,4210 1680,4211.5 R37.1@1680,4276.38
NetR40_2: R40.2 S2.3 | length 104.7
  Top Signal w5: v1(1200,1515) 1200,1540 1210,1550 S2.3@1200,1560
  Bottom Signal w5: v1(1200,1515) R40.2@1200,1566.38
NetR41_2: R41.2 S2.4 | length 94.1
  Top Signal w5: v1(1255,1515) 1255,1555 S2.4@1260,1560
  Bottom Signal w5: v1(1255,1515) 1255,1555 R41.2@1260,1560
NetR42_2: R42.2 R43.2 U7.8 | length 120.9
  Top Signal w5: v1(1112,1056) 1114,1056 U7.8@1150,1020
  Bottom Signal w5: R42.2@1112,1028 v1(1112,1056) ; R42.2@1130,1010 R43.2@1170,1010
NetR54_1: R54.1 U10.5 | length 136
  Top Signal w5: U10.5@1515,721.65 1473.35,721.65 ; R54.1@1460,735 1473.35,721.65 ; R54.1@1460,735 1473.35,721.65 ; R54.1@1460,735 1473.35,721.65 ; R54.1@1460,735 1473.35,721.65 ; R54.1@1460,735 1473.35,721.65
NetR56_2: R56.2 U10.8 | length 136
  Top Signal w5: U10.8@1665,721.65 1706.65,721.65 ; 1706.65,721.65 R56.2@1720,735 ; 1706.65,721.65 R56.2@1720,735 ; 1706.65,721.65 R56.2@1720,735 ; 1706.65,721.65 R56.2@1720,735 ; 1706.65,721.65 R56.2@1720,735
NetR63_2: R63.2 U2.3 | length 341.3
  Top Signal w6: R63.2@1170,5960 1165,5955 1165,5920 1195,5890 1195,5765 1267.4,5692.6 U2.3@1296.85,5692.6
NetR64_2: R64.2 U2.4 | length 351
  Top Signal w6: U2.4@1296.85,5676.85 1336.85,5676.85 1340,5680 1340,5885 1375,5920 1375,5965 R64.2@1370,5970
NetR65_1: R65.1 R66.2 R67.2 U2.70 | length 176.9
  Top Signal w5: U2.70@1900,5317.96 1947.96,5317.96 v1(1950,5320)
  Bottom Signal w5: v1(1950,5320) 1955,5325 R65.1@1980,5325 ; R65.1@1983.19,5323.19 1985,5325 R66.2@2030,5325
  Bottom Signal w6: R66.2@2033.62,5326.38 R67.2@2080,5326.38
NetR68_2: R68.2 U2.59 | length 68.9
  Top Signal w6: R68.2@1763.62,5110 U2.59@1763.62,5178.92
NetR103_2: R103.2 U3.6 | length 104.4
  Top Signal w10: R103.2@548.62,5485 U3.6@652.99,5485
NetR104_2: R104.2 U3.7 | length 104.4
  Top Signal w10: R104.2@548.62,5435 U3.7@652.99,5435
PGA135_GND: J1.2 R23.2 | length 415.9
  Bottom Signal w25: J1.2@250,4050 298,4098 330.1,4098 369.89,4098.01 397,4098 415,4080 R23.2@638.5,4080
PGA246_GND: J5.2 R24.2 | length 432.3
  Bottom Signal w10: R24.2@643.5,1560 R24.2@645,1560
  Bottom Signal w25: J5.2@250,1550 300,1600 380,1600 420,1560 R24.2@643.5,1560
QEP1_SEL: S3.5 U9.9 U9.10 U9.11 | length 534.8
  Top Signal w5: S3.5@860,925 820,965 820,1015 855,1050 855,1325 878.2,1348.2 897.8,1348.2 U9.11@897.8,1348.39 U9.10@897.8,1373.98 U9.9@897.8,1399.57
QEP2_SEL: S3.2 U8.9 U8.10 U8.11 | length 649.5
  Top Signal w5: S3.2@1010,925 1040,925 v1(1065,950) ; v1(1235,1365) 1243.98,1373.98 U8.10@1277.8,1373.98 ; U8.11@1277.8,1348.39 1277.8,1372.8 U8.10@1280,1375 ; U8.10@1277.8,1377.8 U8.9@1277.8,1399.57
  Bottom Signal w5: v1(1065,950) 1070,950 1070,1050 1175,1155 1175,1195 1215,1235 1215,1345 v1(1235,1365)
RXD_FROM_XDS: J101.2 S8.5 | length 459.6
  Top Signal w5: S8.5@1057.17,4205 v1(1125,4205)
  Bottom Signal w5: v1(1125,4205) 1170,4250 1170,4465 J101.2@1250,4545
TCK: J101.8 U1.60 | length 2303.2
  Top Signal w5: v1(980,3960) 980,3580 1200,3360 v1(1200,3270) ; v1(1310,2560) 1310,2520 1300,2510 1300,2456.48 U1.60@1323.3,2433.19
  Bottom Signal w5: J101.8@950,4550 950,4480 980,4450 v1(980,3960) ; v1(1200,3270) 1210,3260 1210,2620 1270,2560 v1(1310,2560)
TMS: J101.6 R10.1 U1.62 | length 2307.3
  Top Signal w5: v1@1000,3980 1000,3590 1240,3350 v1(1240,3270) ; 1325,2498.92 1325,2487.16 U1.62@1351.14,2461.03 ; 1325,2500 1340,2515 v1(1340,2560)
  Bottom Signal w5: v1(1000,3985) 1000,4420 1050,4470 R10.1@1050,4473.62 J101.6@1050,4550 ; v1(1240,3270) 1240,3240 1220,3220 1220,2630 1260,2590 1310,2590 v1(1340,2560)
TXD_TO_XDS: J101.4 S8.2 | length 372.8
  Top Signal w5: J101.4@1150,4550 1150,4255 S8.2@1205,4200
USB_DM: R103.1 U100.5 USB101.2 | length 593.7
  Top Signal w8: USB101.2@419.41,5940 USB101.2@419.41,5948.19 ; USB101.2@420,5940 420,5900 395,5875 v1(395,5860) 395,5855 405,5845 U100.5@423.19,5845 ; v1(440,5490) R103.1@495,5490
  Bottom Signal w8: v1(395,5860) 405,5860 450,5815 450,5500 v1(440,5490)
USB_DP: R104.1 U100.4 USB101.3 | length 629.2
  Top Signal w8: U100.4@423.19,5864.69 423.19,5873.19 445,5895 USB101.3@445,5948.19 ; v1(450,5430) R104.1@496.38,5430 R104.1@500,5430
  Top Signal w12: USB101.3@443.81,5947 USB101.3@445,5948.19
  Bottom Signal w8: v1(443.81,5900) 443.81,5866.19 465,5845 465,5445 v1(450,5430)
USB_GND: C100.2 C101.2 C103.2 C104.2 C105.1 C106.1 JP1.1 L100.2 LED0.1 R100.1 R102.1 U3.2 U3.8 U100.3 U101.6 U101.9@170,5650 | length 1051.6
  Top Signal w8: v1(365,5420) LED0.1@365,5463.66 ; U100.3@446.81,5864.69 464.69,5864.69 475,5875 v1@475,5880 ; v1@474,5880 v1@474,5881
  Top Signal w12: R102.1@143.62,5530 144.62,5529 v1(187,5529) ; U101.6@157.2,5594.88 157.2,5567.8 165,5560 v1(175,5560)
  Top Signal w20: C103.2@80,5646.38 U101.9@166.38,5646.38 ; v1(565,5280) 648.74,5280 C104.2@650,5278.74 ; v1(585,5385) U3.8@652.99,5385 653.99,5384 v1(717,5384) ; v1(650,5330) C104.2@650,5278.74 ; v1(730,5280) 651.26,5280 C104.2@650,5278.74
  Top Signal w25: v1(415,5685) U3.2@652.99,5685 v1(716,5685) ; v1(585,5825) 591.5,5831.5 L100.2@591.5,5870 ; v1(660,5850) R100.1@660,5896.38 ; v1(710,5850) C101.2@710,5896.38
  other v1: 478,5876
  other v2: 170,5627.36 132.6,5650 207.4,5650 170,5672.64
USB_ID: U100.2 USB101.4 | length 156
  Top Signal w8: U100.2@446.81,5845 480,5845 498,5863 498,5888.87 471.87,5915 471.87,5943.13 USB101.4@470.59,5944.41 ; USB101.4@470,5945 USB101.4@470.59,5944.41 ; USB101.4@470.59,5948.19 USB101.4@470.59,5944.41
USB_VBUS: C100.1 C105.2 JP3.1 L101.2 U3.1 U100.6 U101.1 U101.2 U101.8 | length 460.1
  Top Signal w5: v1(395,5825) 400,5825 400.31,5825.31 U100.6@423.19,5825.31
  Top Signal w10: L101.2@260,5828.5 L101.2@261.5,5830
  Top Signal w12: U101.2@182.8,5705.12 195,5717.32 195,5718.5 ; v1(195,5740) 195,5718.5 ; v1(208.39,5571.61) U101.8@208.39,5594.88 ; U101.1@208.39,5705.12 195,5718.5
  Top Signal w20: v1(260,5780) L101.2@260,5828.5 ; v1(420,5730) 422.76,5730 426.38,5733.62 C100.1@460,5733.62
  Top Signal w25: C100.1@460,5733.62 C105.2@560,5733.62 651.61,5733.62 U3.1@652.99,5735 v1(717,5735)
USB_VCC: C102.1 C103.1 JP2.1 R101.2 R105.2 U101.3 U101.4
VDD: C9.2 C10.2 C11.1 C12.1 C13.1 C14.1 TP1.1 U1.4 U1.46 U1.71 U1.87 | length 605.6
  Top Signal w10: v1(1035,3065) 1035,3055.55 U1.4@1060.22,3030.33 ; U1.46@1046.3,2363.59 v1@1082.71,2400 ; U1.87@1378.97,2891.14 1411.84,2924 v1(1414,2924) ; U1.71@1476.41,2586.3 1522.71,2540 v1(1530,2540)
  Bottom Signal w10: C10.2@1020,3100 C10.2@1022.27,3097.73 ; C10.2@1020,3105 C10.2@1022.5,3102.5 ; C10.2@1022.27,3102.27 C10.2@1022.27,3097.73 ; C14.1@1065,3055 C14.1@1070,3050 ; C14.1@1070,3045 1050,3065 v1(1035,3065) 1035,3085 C10.2@1022.27,3097.73 ; v1(1080,2400) C13.1@1160,2400 ; C13.1@1160,2396.38 1165,2391.38 v1(1165,2360) ; v1(1414,2924) 1419,2924 1440,2945 C11.1@1440,2955 ; C11.1@1443.3,2951.7 1443.3,2958.3 1485,3000 C9.2@1468,3000 ; C12.1@1493.3,2553.3 1506.7,2553.3 1520,2540 v1(1530,2540)
VDDA: C16.1 C17.1 C18.1 L2.2 TP3.1 U1.11 U1.34 | length 320.6
  Top Signal w10: U1.34@879.27,2530.62 880.62,2530.62 v1(919,2569) ; U1.11@962.78,2932.89 1000,2895.68 v1(1000,2890) ; v1(919,2569) 918.18,2569.82 v1(919,2569)
  Bottom Signal w10: L2.2@643.46,2770 v1(690,2770) ; v1(919,2569) 967.5,2569 968.32,2569.82 C16.1@968.5,2570 ; v1@997.73,2892.27 1047.73,2892.27 1010,2854.54 1010,2850
VDDIO: C20.1 C21.2 C22.2 C23.2 C24.2 C25.2 L3.2 TP2.1 U1.3 U1.47 U1.70 U1.80 U1.88 | length 637.7
  Top Signal w6: v1(1023,2314) 1024.55,2314 U1.47@1060.22,2349.67 ; v1(1300,2860) 1320,2860 U1.88@1365.06,2905.06 ; v1(1405,2635) 1405,2630 1435,2600 ; 1434.94,2599.94 U1.70@1462.49,2572.38 ; v1(1448,2755) 1448,2768 1473.7,2793.7 U1.80@1476.41,2793.7
  Top Signal w10: U1.3@1080,3040 1100,3020 v1(1100,3003.41)
  Bottom Signal w6: v1(1023,2314) 1023,2339 C22.2@1037,2353 ; v1@1100,3005 v1(1100,3003.41) 1100,2993.41 C21.2@1126.7,2966.7 ; v1(1300,2860) C24.2@1325,2885 ; v1(1306,2725) v1@1307,2725 ; v1@1307,2726 1308.73,2727.73 C20.1@1352.27,2727.73 ; C20.1@1352.5,2727.5 C20.1@1355,2730 ; v1(1405,2635) 1431.7,2608.3 C23.2@1433.3,2608.3 ; C25.2@1412,2747 1420,2755 v1(1448,2755)
  Bottom Signal w10: L3.2@1000,2263.46 L3.2@1010,2263.46 L3.2@1011,2263.46 ; L3.2@1011,2263 v1(1060,2263)
VREGENZ: R11.1 R12.1 U1.73 | length 205
  Top Signal w5: U1.73@1504.25,2614.14 1528.39,2590 1620,2590 R11.1@1628.5,2581.5 ; R12.1@1628,2517 1628.5,2517.5 R11.1@1628.5,2581.5 ; R11.1@1628.5,2584 R11.1@1628.5,2581.5
X1: C39.1 R35.1 U1.69 Y2.3 | length 436.2
  Top Signal w6: U1.69@1448.57,2558.46 1470.88,2536.16 1503.84,2536.16 1593.22,2446.78
  Top Signal w8: 1593.22,2446.78 1633.76,2406.24 Y2.3@1650.71,2406.24 ; v1(1633,2362) 1654.05,2383.05 Y2.3@1654.05,2406.24
  Bottom Signal w0: v1@1632.43,2360 1633,2360.57 v1@1634.43,2362
  Bottom Signal w8: v1@1632.43,2360 1630,2360 1672.93,2402.93 C39.1@1674.84,2402.93 ; v1(1633,2362) 1633,2360.57 1633,2354 1640.86,2346.14 R35.1@1671.92,2346.14
XDS_DM: R1.2 U2.93 | length 900.2
  Top Signal w6: v1(1200,5460) 1190,5460 R1.2@1160,5490 ; v1(1360,5400) 1485,5400 1761.85,5676.85 U2.93@1903.15,5676.85 ; R1.2@1160,5490 1161.81,5488.19 R1.2@1160,5490
  Bottom Signal w6: v1(1200,5460) 1260,5400 v1(1360,5400)
XDS_DP: R2.2 U2.94 | length 851.9
  Top Signal w6: R2.2@1160,5430 R2.2@1163.62,5430 1200,5430 1210,5440 v1(1250,5440) ; v1(1390,5440) 1501,5440 1753.6,5692.6 U2.94@1903.15,5692.6
  Bottom Signal w6: v1(1250,5440) v1(1390,5440)
XDS_RESET_OUT: J102.10 R57.1 U2.40 U12.2 | length 515.2
  Top Signal w5: U12.2@1456.57,4980 v1(1490,4980) 1490,4875 1480,4865 1550,4795 J102.10@1550,4750 ; U2.40@1466.14,5176.85 1466.14,5123.86 v1(1470,5120) ; J102.10@1548.62,4748.62 J102.10@1550,4750 ; J102.10@1550,4740 J102.10@1550,4750
  Bottom Signal w5: v1(1470,5120) 1470,5010 1490,4990 v1(1490,4980)
XDS_RXD: J101.3 U2.33 | length 612.1
  Top Signal w5: J101.3@1150,4650 1150,4930 1355.91,5135.91 U2.33@1355.91,5176.85
XDS_TCK_SWDCLK: J101.7 J102.4 U2.35 U12.6 | length 1444.2
  Top Signal w5: U2.35@1387.4,5176.85 1387.4,5107.4 1370,5090 v1(1370,4980) ; U12.6@1410,4980 U12.6@1403.43,4980 v1(1370,4980) ; J102.4@1700,4735 J102.4@1700,4734.88 1700,4680 1690,4670 1525,4670 1370,4825 v1(1370,4980)
  Bottom Signal w5: J101.7@950,4650 950,4710 1080,4840 1230,4840 v1(1370,4980)
XDS_TDI: J102.8 U2.38 U12.3 | length 557.9
  Top Signal w5: U2.38@1436.03,5173.97 1436.03,5150 1440,5146.03 1440,5070 1460,5050 1460,5003.11 U12.3@1456.57,4999.68 1505.32,4999.68 1515,4990 1515,4850 1565,4800 1590,4800 1600,4790 J102.8@1600,4734.88 J102.8@1600,4730
XDS_TDO_SWO: J102.6 U2.37 U12.5 | length 652.6
  Top Signal w5: U12.5@1403.43,4999.68 1403.43,5033.43 v1@1420,5050 ; v1(1420,5060) v1@1420,5050 ; U2.37@1420,5180 v1@1420,5050 ; J102.6@1650,4735 v1(1650,4815)
  Bottom Signal w5: v1(1420,5060) 1420,4990 1451,4959 1465,4959 1599,4825 1645,4825 1650,4820 v1(1650,4815)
